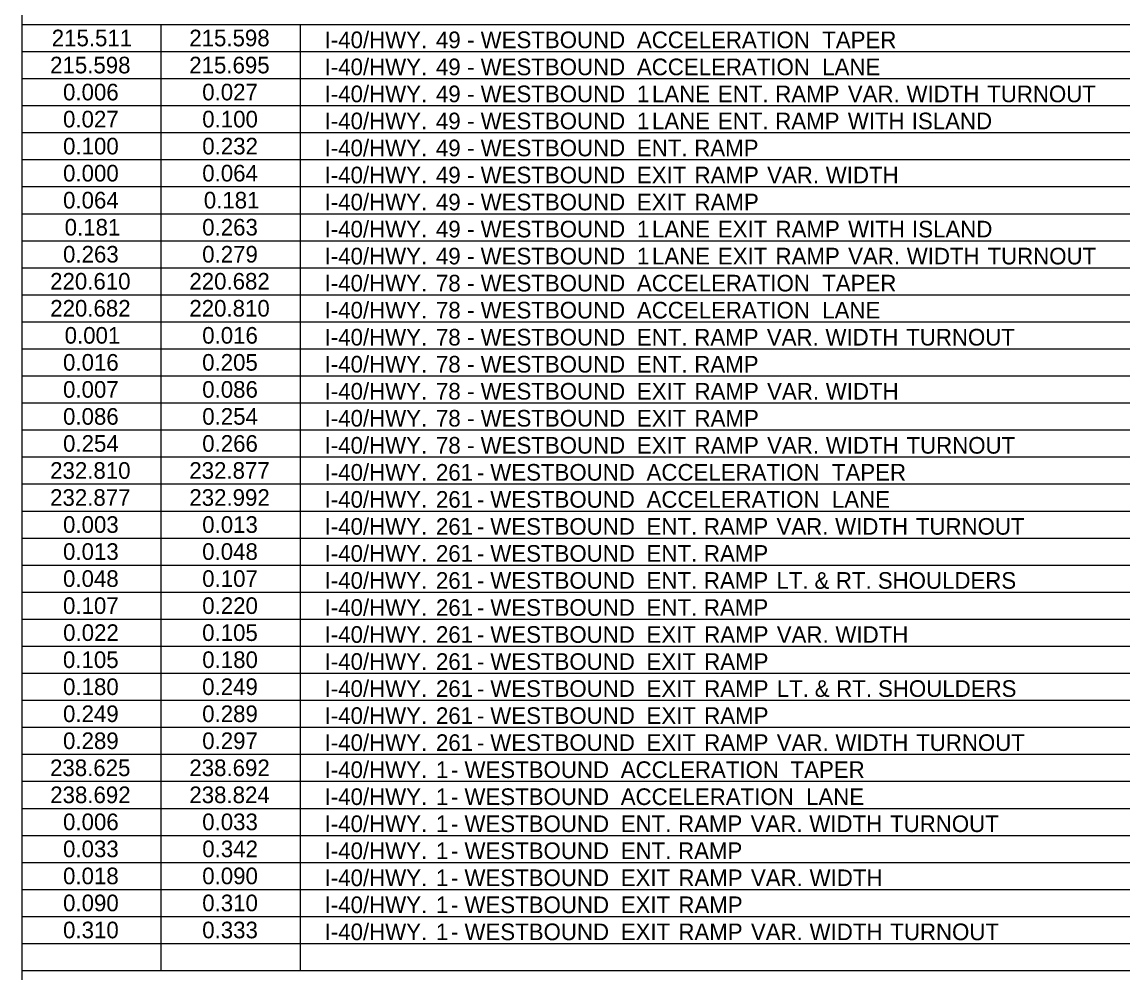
# Model space of a CAD drawing. Extents: x 2261867 to 2275370, y -3124789 to -3122260.
# Drawn here: x 2267341.3 to 2267666.7, y -3124303.8 to -3124022.5 of the extents above; entities that cross this region are included whole.
import ezdxf

# ---------------------------------------------------------------- set-up
doc = ezdxf.new("R2010")
doc.units = 0
doc.layers.add('Default', color=7, linetype='Continuous')

msp = doc.modelspace()

# ---------------------------------------------------------------- linework, layer by layer
at = {"layer": 'Default'}
for p, q in [((2267341.29, -3124734.8), (2267341.29, -3123799.38)), ((2267341.29, -3124734.8), (2267341.29, -3123799.38)), ((2267341.29, -3124023.24), (2267822.99, -3124023.24)), ((2267341.29, -3124023.24), (2267423.64, -3124023.24)), ((2267382.46, -3124303.07), (2267382.46, -3124023.24)), ((2267423.64, -3124303.07), (2267423.64, -3124023.24)), ((2267423.64, -3124303.07), (2267423.64, -3124023.24)), ((2267341.29, -3124031.24), (2267781.81, -3124031.24)), ((2267382.46, -3124303.07), (2267382.46, -3124031.24)), ((2267341.29, -3124039.23), (2267781.81, -3124039.23)), ((2267341.29, -3124047.23), (2267781.81, -3124047.23)), ((2267341.29, -3124055.22), (2267781.81, -3124055.22)), ((2267341.29, -3124063.22), (2267781.81, -3124063.22)), ((2267341.29, -3124071.21), (2267781.81, -3124071.21)), ((2267341.29, -3124079.21), (2267781.81, -3124079.21)), ((2267341.29, -3124087.2), (2267781.81, -3124087.2)), ((2267341.29, -3124095.2), (2267781.81, -3124095.2)), ((2267341.29, -3124103.19), (2267781.81, -3124103.19)), ((2267341.29, -3124111.19), (2267781.81, -3124111.19)), ((2267341.29, -3124119.18), (2267781.81, -3124119.18)), ((2267341.29, -3124127.18), (2267781.81, -3124127.18)), ((2267341.29, -3124135.17), (2267781.81, -3124135.17)), ((2267341.29, -3124143.17), (2267781.81, -3124143.17)), ((2267341.29, -3124151.16), (2267781.81, -3124151.16)), ((2267341.29, -3124159.16), (2267781.81, -3124159.16)), ((2267341.29, -3124167.15), (2267781.81, -3124167.15)), ((2267341.29, -3124175.15), (2267781.81, -3124175.15)), ((2267341.29, -3124183.14), (2267781.81, -3124183.14)), ((2267341.29, -3124191.14), (2267781.81, -3124191.14)), ((2267341.29, -3124199.13), (2267781.81, -3124199.13)), ((2267341.29, -3124207.13), (2267781.81, -3124207.13)), ((2267341.29, -3124215.12), (2267781.81, -3124215.12)), ((2267341.29, -3124223.12), (2267781.81, -3124223.12)), ((2267341.29, -3124231.11), (2267781.81, -3124231.11)), ((2267341.29, -3124239.11), (2267781.81, -3124239.11)), ((2267341.29, -3124247.1), (2267781.81, -3124247.1)), ((2267341.29, -3124255.1), (2267781.81, -3124255.1)), ((2267341.29, -3124263.09), (2267781.81, -3124263.09)), ((2267341.29, -3124271.09), (2267781.81, -3124271.09)), ((2267341.29, -3124279.08), (2267781.81, -3124279.08)), ((2267341.29, -3124287.08), (2267781.81, -3124287.08)), ((2267341.29, -3124295.07), (2267781.81, -3124295.07)), ((2267341.29, -3124303.07), (2267677.48, -3124303.07)), ((2267341.29, -3124303.07), (2267822.99, -3124303.07))]:
    msp.add_line(p, q, dxfattribs=at)

# ---------------------------------------------------------------- texts
for s, p in [('215.511', (2267350.09, -3124029.7)), ('215.598', (2267390.78, -3124029.7)), ('I-40/HWY.', (2267430.83, -3124030.25)), (' 49', (2267461.93, -3124030.25)), (' WESTBOUND', (2267475.16, -3124030.25)), (' ACCELERATION', (2267521.39, -3124030.25)), (' TAPER', (2267576.22, -3124030.25)), (' -', (2267471.17, -3124030.25)), ('215.598', (2267349.61, -3124037.7)), ('215.695', (2267390.77, -3124037.7)), ('I-40/HWY.', (2267430.83, -3124038.25)), (' 49', (2267461.93, -3124038.25)), (' WESTBOUND', (2267475.16, -3124038.25)), (' ACCELERATION', (2267521.39, -3124038.25)), (' LANE', (2267576.22, -3124038.25)), (' -', (2267471.17, -3124038.25)), ('0.006', (2267353.43, -3124045.69)), ('0.027', (2267394.61, -3124045.69)), ('I-40/HWY.', (2267430.83, -3124046.24)), (' 49', (2267461.93, -3124046.24)), (' WESTBOUND', (2267475.16, -3124046.24)), (' 1', (2267521.39, -3124046.24)), (' LANE', (2267525.85, -3124046.24)), (' ENT.', (2267545.35, -3124046.24)), (' RAMP', (2267562.32, -3124046.24)), (' VAR.', (2267583.79, -3124046.24)), (' WIDTH', (2267601.15, -3124046.24)), (' TURNOUT', (2267625.03, -3124046.24)), (' -', (2267471.17, -3124046.24)), ('0.027', (2267353.43, -3124053.69)), ('0.100', (2267394.62, -3124053.69)), ('I-40/HWY.', (2267430.83, -3124054.24)), (' 49', (2267461.93, -3124054.24)), (' WESTBOUND', (2267475.16, -3124054.24)), (' 1', (2267521.39, -3124054.24)), (' LANE', (2267525.85, -3124054.24)), (' ENT.', (2267545.35, -3124054.24)), (' RAMP', (2267562.32, -3124054.24)), (' WITH', (2267583.79, -3124054.24)), (' ISLAND', (2267602.71, -3124054.24)), (' -', (2267471.17, -3124054.24)), ('0.100', (2267353.44, -3124061.68)), ('0.232', (2267394.63, -3124061.68)), ('I-40/HWY.', (2267430.83, -3124062.23)), (' 49', (2267461.93, -3124062.23)), (' WESTBOUND', (2267475.16, -3124062.23)), (' ENT.', (2267521.39, -3124062.23)), (' RAMP', (2267538.36, -3124062.23)), (' -', (2267471.17, -3124062.23)), ('0.000', (2267353.44, -3124069.68)), ('0.064', (2267394.62, -3124069.68)), ('I-40/HWY.', (2267430.83, -3124070.23)), (' 49', (2267461.93, -3124070.23)), (' WESTBOUND', (2267475.16, -3124070.23)), (' EXIT', (2267521.39, -3124070.23)), (' RAMP', (2267538.44, -3124070.23)), (' VAR.', (2267559.91, -3124070.23)), (' WIDTH', (2267577.27, -3124070.23)), (' -', (2267471.17, -3124070.23)), ('0.064', (2267353.44, -3124077.67)), ('0.181', (2267395.08, -3124077.67)), ('I-40/HWY.', (2267430.83, -3124078.22)), (' 49', (2267461.93, -3124078.22)), (' -', (2267471.17, -3124078.22)), (' WESTBOUND', (2267475.16, -3124078.22)), (' EXIT', (2267521.39, -3124078.22)), (' RAMP', (2267538.44, -3124078.22)), ('0.181', (2267353.91, -3124085.67)), ('0.263', (2267394.61, -3124085.67)), ('I-40/HWY.', (2267430.83, -3124086.22)), (' 49', (2267461.93, -3124086.22)), (' WESTBOUND', (2267475.16, -3124086.22)), (' 1', (2267521.39, -3124086.22)), (' LANE', (2267525.85, -3124086.22)), (' EXIT', (2267545.35, -3124086.22)), (' RAMP', (2267562.4, -3124086.22)), (' WITH', (2267583.88, -3124086.22)), (' ISLAND', (2267602.79, -3124086.22)), (' -', (2267471.17, -3124086.22)), ('0.263', (2267353.43, -3124093.66)), ('0.279', (2267394.6, -3124093.66)), ('I-40/HWY.', (2267430.83, -3124094.21)), (' 49', (2267461.93, -3124094.21)), (' WESTBOUND', (2267475.16, -3124094.21)), (' TURNOUT', (2267625.11, -3124094.21)), (' -', (2267471.17, -3124094.21)), (' 1', (2267521.39, -3124094.21)), (' LANE', (2267525.85, -3124094.21)), (' EXIT', (2267545.35, -3124094.21)), (' RAMP', (2267562.4, -3124094.21)), (' VAR.', (2267583.88, -3124094.21)), (' WIDTH', (2267601.23, -3124094.21)), ('220.610', (2267349.62, -3124101.66)), ('220.682', (2267390.81, -3124101.66)), ('I-40/HWY.', (2267430.83, -3124102.21)), (' 78', (2267461.93, -3124102.21)), (' WESTBOUND', (2267475.16, -3124102.21)), (' ACCELERATION', (2267521.39, -3124102.21)), (' TAPER', (2267576.22, -3124102.21)), (' -', (2267471.17, -3124102.21)), ('220.682', (2267349.64, -3124109.65)), ('220.810', (2267390.8, -3124109.65)), ('I-40/HWY.', (2267430.83, -3124110.2)), (' 78', (2267461.93, -3124110.2)), (' WESTBOUND', (2267475.16, -3124110.2)), (' ACCELERATION', (2267521.39, -3124110.2)), (' LANE', (2267576.22, -3124110.2)), (' -', (2267471.17, -3124110.2)), ('0.001', (2267353.91, -3124117.65)), ('0.016', (2267394.61, -3124117.65)), ('I-40/HWY.', (2267430.83, -3124118.2)), (' 78', (2267461.93, -3124118.2)), (' WESTBOUND', (2267475.16, -3124118.2)), (' ENT.', (2267521.39, -3124118.2)), (' RAMP', (2267538.36, -3124118.2)), (' VAR.', (2267559.83, -3124118.2)), (' WIDTH', (2267577.18, -3124118.2)), (' TURNOUT', (2267601.06, -3124118.2)), (' -', (2267471.17, -3124118.2)), ('0.016', (2267353.43, -3124125.64)), ('0.205', (2267394.59, -3124125.64)), ('I-40/HWY.', (2267430.83, -3124126.19)), (' 78', (2267461.93, -3124126.19)), (' WESTBOUND', (2267475.16, -3124126.19)), (' ENT.', (2267521.39, -3124126.19)), (' RAMP', (2267538.36, -3124126.19)), (' -', (2267471.17, -3124126.19)), ('0.007', (2267353.43, -3124133.64)), ('0.086', (2267394.61, -3124133.64)), ('I-40/HWY.', (2267430.83, -3124134.19)), (' 78', (2267461.93, -3124134.19)), (' WESTBOUND', (2267475.16, -3124134.19)), (' EXIT', (2267521.39, -3124134.19)), (' RAMP', (2267538.44, -3124134.19)), (' VAR.', (2267559.91, -3124134.19)), (' WIDTH', (2267577.27, -3124134.19)), (' -', (2267471.17, -3124134.19)), ('0.086', (2267353.43, -3124141.63)), ('0.254', (2267394.62, -3124141.63)), ('I-40/HWY.', (2267430.83, -3124142.18)), (' 78', (2267461.93, -3124142.18)), (' WESTBOUND', (2267475.16, -3124142.18)), (' EXIT', (2267521.39, -3124142.18)), (' RAMP', (2267538.44, -3124142.18)), (' -', (2267471.17, -3124142.18)), ('0.254', (2267353.44, -3124149.63)), ('0.266', (2267394.61, -3124149.63)), ('I-40/HWY.', (2267430.83, -3124150.18)), (' 78', (2267461.93, -3124150.18)), (' WESTBOUND', (2267475.16, -3124150.18)), (' EXIT', (2267521.39, -3124150.18)), (' RAMP', (2267538.44, -3124150.18)), (' VAR.', (2267559.91, -3124150.18)), (' WIDTH', (2267577.27, -3124150.18)), (' TURNOUT', (2267601.15, -3124150.18)), (' -', (2267471.17, -3124150.18)), ('232.810', (2267349.62, -3124157.62)), ('232.877', (2267390.79, -3124157.62)), ('I-40/HWY.', (2267430.83, -3124158.17)), (' 261', (2267461.93, -3124158.17)), (' WESTBOUND', (2267478.02, -3124158.17)), (' ACCELERATION', (2267524.25, -3124158.17)), (' TAPER', (2267579.08, -3124158.17)), (' -', (2267474.04, -3124158.17)), ('232.877', (2267349.61, -3124165.62)), ('232.992', (2267390.81, -3124165.62)), ('I-40/HWY.', (2267430.83, -3124166.17)), (' 261', (2267461.93, -3124166.17)), (' -', (2267474.04, -3124166.17)), (' WESTBOUND', (2267478.02, -3124166.17)), (' ACCELERATION', (2267524.25, -3124166.17)), (' LANE', (2267579.08, -3124166.17)), ('0.003', (2267353.43, -3124173.61)), ('0.013', (2267394.61, -3124173.61)), ('I-40/HWY.', (2267430.83, -3124174.16)), (' 261', (2267461.93, -3124174.16)), (' WESTBOUND', (2267478.02, -3124174.16)), (' ENT.', (2267524.25, -3124174.16)), (' RAMP', (2267541.22, -3124174.16)), (' VAR.', (2267562.69, -3124174.16)), (' WIDTH', (2267580.04, -3124174.16)), (' TURNOUT', (2267603.92, -3124174.16)), (' -', (2267474.04, -3124174.16)), ('0.013', (2267353.43, -3124181.61)), ('0.048', (2267394.6, -3124181.61)), ('I-40/HWY.', (2267430.83, -3124182.16)), (' 261', (2267461.93, -3124182.16)), (' -', (2267474.04, -3124182.16)), (' WESTBOUND', (2267478.02, -3124182.16)), (' ENT.', (2267524.25, -3124182.16)), (' RAMP', (2267541.22, -3124182.16)), ('0.048', (2267353.43, -3124189.6)), ('0.107', (2267394.61, -3124189.6)), ('I-40/HWY.', (2267430.83, -3124190.15)), (' 261', (2267461.93, -3124190.15)), (' WESTBOUND', (2267478.02, -3124190.15)), (' ENT.', (2267524.25, -3124190.15)), (' RAMP', (2267541.22, -3124190.15)), (' LT.', (2267562.69, -3124190.15)), (' &', (2267573.93, -3124190.15)), (' RT.', (2267580.27, -3124190.15)), (' SHOULDERS', (2267592.65, -3124190.15)), (' -', (2267474.04, -3124190.15)), ('0.107', (2267353.43, -3124197.6)), ('0.220', (2267394.62, -3124197.6)), ('I-40/HWY.', (2267430.83, -3124198.15)), (' 261', (2267461.93, -3124198.15)), (' WESTBOUND', (2267478.02, -3124198.15)), (' ENT.', (2267524.25, -3124198.15)), (' RAMP', (2267541.22, -3124198.15)), (' -', (2267474.04, -3124198.15)), ('0.022', (2267353.46, -3124205.59)), ('0.105', (2267394.59, -3124205.59)), ('I-40/HWY.', (2267430.83, -3124206.14)), (' 261', (2267461.93, -3124206.14)), (' WESTBOUND', (2267478.02, -3124206.14)), (' EXIT', (2267524.25, -3124206.14)), (' RAMP', (2267541.3, -3124206.14)), (' VAR.', (2267562.77, -3124206.14)), (' WIDTH', (2267580.13, -3124206.14)), (' -', (2267474.04, -3124206.14)), ('0.105', (2267353.41, -3124213.59)), ('0.180', (2267394.62, -3124213.59)), ('I-40/HWY.', (2267430.83, -3124214.14)), (' 261', (2267461.93, -3124214.14)), (' WESTBOUND', (2267478.02, -3124214.14)), (' EXIT', (2267524.25, -3124214.14)), (' RAMP', (2267541.3, -3124214.14)), (' -', (2267474.04, -3124214.14)), ('0.180', (2267353.44, -3124221.58)), ('0.249', (2267394.6, -3124221.58)), ('I-40/HWY.', (2267430.83, -3124222.13)), (' 261', (2267461.93, -3124222.13)), (' WESTBOUND', (2267478.02, -3124222.13)), (' EXIT', (2267524.25, -3124222.13)), (' RAMP', (2267541.3, -3124222.13)), (' LT.', (2267562.77, -3124222.13)), (' &', (2267574.01, -3124222.13)), (' RT.', (2267580.35, -3124222.13)), (' SHOULDERS', (2267592.73, -3124222.13)), (' -', (2267474.04, -3124222.13)), ('0.249', (2267353.43, -3124229.58)), ('0.289', (2267394.6, -3124229.58)), ('I-40/HWY.', (2267430.83, -3124230.13)), (' 261', (2267461.93, -3124230.13)), (' WESTBOUND', (2267478.02, -3124230.13)), (' EXIT', (2267524.25, -3124230.13)), (' RAMP', (2267541.3, -3124230.13)), (' -', (2267474.04, -3124230.13)), ('0.289', (2267353.43, -3124237.57)), ('0.297', (2267394.61, -3124237.57)), ('I-40/HWY.', (2267430.83, -3124238.12)), (' 261', (2267461.93, -3124238.12)), (' WESTBOUND', (2267478.02, -3124238.12)), (' EXIT', (2267524.25, -3124238.12)), (' RAMP', (2267541.3, -3124238.12)), (' VAR.', (2267562.77, -3124238.12)), (' WIDTH', (2267580.13, -3124238.12)), (' TURNOUT', (2267604.01, -3124238.12)), (' -', (2267474.04, -3124238.12)), ('238.625', (2267349.59, -3124245.57)), ('238.692', (2267390.81, -3124245.57)), ('I-40/HWY.', (2267430.83, -3124246.12)), (' 1', (2267461.93, -3124246.12)), (' WESTBOUND', (2267470.38, -3124246.12)), (' ACCLERATION', (2267516.61, -3124246.12)), (' TAPER', (2267566.85, -3124246.12)), (' -', (2267466.39, -3124246.12)), ('238.692', (2267349.64, -3124253.56)), ('238.824', (2267390.8, -3124253.56)), ('I-40/HWY.', (2267430.83, -3124254.11)), (' 1', (2267461.93, -3124254.11)), (' -', (2267466.39, -3124254.11)), (' WESTBOUND', (2267470.38, -3124254.11)), (' ACCELERATION', (2267516.61, -3124254.11)), (' LANE', (2267571.43, -3124254.11)), ('0.006', (2267353.43, -3124261.56)), ('0.033', (2267394.61, -3124261.56)), ('I-40/HWY.', (2267430.83, -3124262.11)), (' 1', (2267461.93, -3124262.11)), (' WESTBOUND', (2267470.38, -3124262.11)), (' ENT.', (2267516.61, -3124262.11)), (' RAMP', (2267533.57, -3124262.11)), (' VAR.', (2267555.05, -3124262.11)), (' WIDTH', (2267572.4, -3124262.11)), (' TURNOUT', (2267596.28, -3124262.11)), (' -', (2267466.39, -3124262.11)), ('0.033', (2267353.43, -3124269.55)), ('0.342', (2267394.63, -3124269.55)), ('I-40/HWY.', (2267430.83, -3124270.1)), (' 1', (2267461.93, -3124270.1)), (' -', (2267466.39, -3124270.1)), (' WESTBOUND', (2267470.38, -3124270.1)), (' ENT.', (2267516.61, -3124270.1)), (' RAMP', (2267533.57, -3124270.1)), ('0.018', (2267353.43, -3124277.55)), ('0.090', (2267394.62, -3124277.55)), ('I-40/HWY.', (2267430.83, -3124278.1)), (' 1', (2267461.93, -3124278.1)), (' WESTBOUND', (2267470.38, -3124278.1)), (' EXIT', (2267516.61, -3124278.1)), (' RAMP', (2267533.66, -3124278.1)), (' VAR.', (2267555.13, -3124278.1)), (' WIDTH', (2267572.48, -3124278.1)), (' -', (2267466.39, -3124278.1)), ('0.090', (2267353.44, -3124285.54)), ('0.310', (2267394.62, -3124285.54)), ('I-40/HWY.', (2267430.83, -3124286.09)), (' 1', (2267461.93, -3124286.09)), (' WESTBOUND', (2267470.38, -3124286.09)), (' EXIT', (2267516.61, -3124286.09)), (' RAMP', (2267533.66, -3124286.09)), (' -', (2267466.39, -3124286.09)), ('0.310', (2267353.44, -3124293.54)), ('0.333', (2267394.61, -3124293.54)), ('I-40/HWY.', (2267430.83, -3124294.09)), (' 1', (2267461.93, -3124294.09)), (' WESTBOUND', (2267470.38, -3124294.09)), (' EXIT', (2267516.61, -3124294.09)), (' RAMP', (2267533.66, -3124294.09)), (' VAR.', (2267555.13, -3124294.09)), (' WIDTH', (2267572.48, -3124294.09)), (' TURNOUT', (2267596.36, -3124294.09)), (' -', (2267466.39, -3124294.09))]:
    msp.add_text(s, height=4.92, dxfattribs=at).set_placement(p)

doc.saveas('drawing.dxf')
